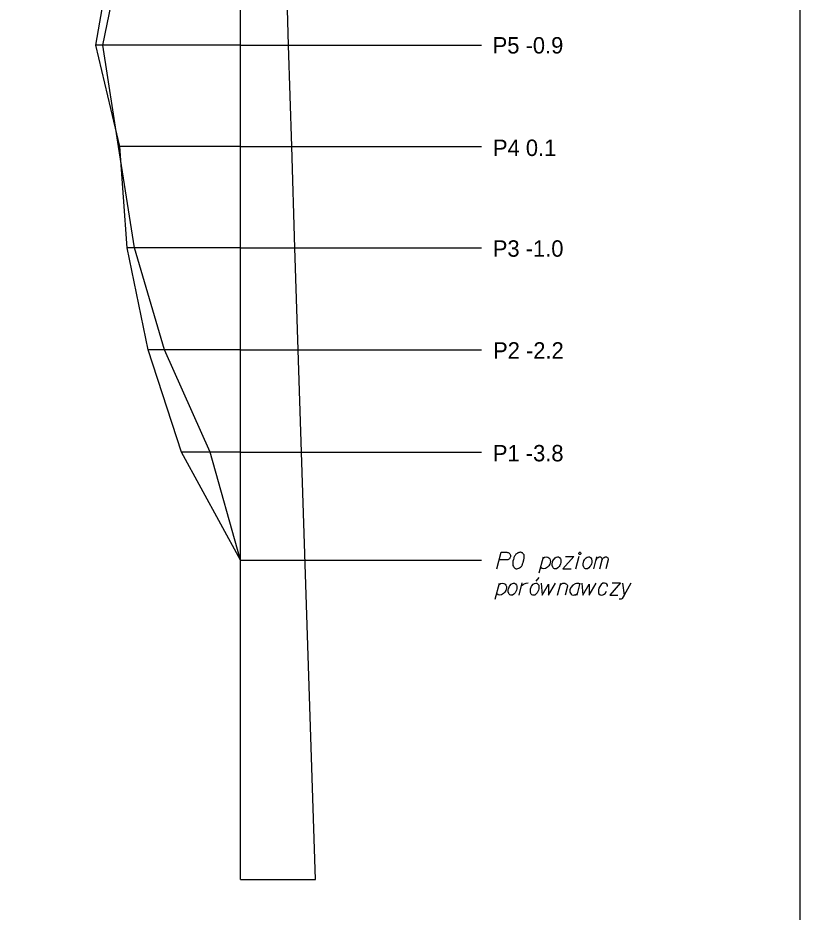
# Model space of a CAD drawing. Extents: x 138 to 264, y -75 to 121.
# Drawn here: x 206.91 to 217.41, y -57.33 to -45.34 of the extents above; entities that cross this region are included whole.
import ezdxf

# ---------------------------------------------------------------- set-up
doc = ezdxf.new("R2010")
doc.units = 0
for name, color, linetype in [('15 listopad 2008', 7, 'Continuous'), ('Ramka do drukowania', 7, 'Continuous'), ('Standart wykresów', 7, 'Continuous'), ('Wykresy 4 maj 2008', 7, 'Continuous')]:
    doc.layers.add(name, color=color, linetype=linetype)

msp = doc.modelspace()

# ---------------------------------------------------------------- linework, layer by layer
at = {"layer": '15 listopad 2008'}
msp.add_lwpolyline([(209.897, -52.61), (209.107, -51.164), (208.657, -49.788), (208.377, -48.421), (208.277, -47.063), (207.957, -45.704), (208.197, -44.313), (208.427, -42.911), (208.387, -41.918), (208.237, -40.937), (208.377, -40.478), (207.757, -39.961), (207.377, -39.493), (206.327, -38.925), (205.867, -38.4), (205.357, -38.212), (202.267, -37.514), (200.467, -37.151), (198.667, -36.895)], dxfattribs=at)
at = {"layer": 'Ramka do drukowania'}
msp.add_line((217.41, -63.621), (217.41, -33.921), dxfattribs=at)
at = {"layer": 'Standart wykresów'}
for p, q in [((209.897, -56.895), (209.897, -36.811)), ((210.544, -45.704), (210.5, -44.313)), ((209.897, -45.704), (213.134, -45.704)), ((210.587, -47.063), (210.544, -45.704)), ((209.897, -47.063), (213.134, -47.063)), ((210.629, -48.421), (210.587, -47.063)), ((209.897, -48.421), (213.134, -48.421)), ((210.671, -49.788), (210.629, -48.421)), ((209.897, -49.788), (213.134, -49.788)), ((210.716, -51.164), (210.671, -49.788)), ((209.897, -51.164), (209.107, -51.164)), ((209.897, -51.164), (213.134, -51.164)), ((210.904, -56.895), (210.716, -51.164)), ((209.897, -52.61), (213.134, -52.61)), ((209.897, -56.895), (210.904, -56.895))]:
    msp.add_line(p, q, dxfattribs=at)
for points in [[(213.341, -52.725), (213.399, -52.505), (213.474, -52.505), (213.484, -52.507), (213.489, -52.509), (213.5, -52.514), (213.507, -52.519), (213.512, -52.526), (213.517, -52.535), (213.521, -52.547), (213.522, -52.557), (213.521, -52.566), (213.519, -52.573), (213.515, -52.58), (213.512, -52.585), (213.507, -52.592), (213.5, -52.597), (213.495, -52.6), (213.486, -52.604), (213.477, -52.606), (213.373, -52.606)], [(213.656, -52.505), (213.652, -52.505), (213.642, -52.507), (213.635, -52.509), (213.63, -52.51), (213.621, -52.514), (213.611, -52.519), (213.602, -52.524), (213.593, -52.531), (213.588, -52.538), (213.583, -52.547), (213.578, -52.555), (213.573, -52.566), (213.569, -52.573), (213.566, -52.583), (213.561, -52.6), (213.555, -52.626), (213.552, -52.647), (213.552, -52.666), (213.554, -52.68), (213.561, -52.696), (213.566, -52.704), (213.574, -52.715), (213.585, -52.722), (213.59, -52.723), (213.6, -52.725), (213.609, -52.725), (213.623, -52.723), (213.635, -52.72), (213.644, -52.715), (213.656, -52.706), (213.661, -52.701), (213.668, -52.694), (213.673, -52.687), (213.677, -52.682), (213.68, -52.673), (213.682, -52.67), (213.685, -52.661), (213.689, -52.651), (213.692, -52.64), (213.694, -52.633), (213.696, -52.628), (213.697, -52.621), (213.701, -52.606), (213.703, -52.597), (213.704, -52.588), (213.706, -52.576), (213.708, -52.56), (213.708, -52.555), (213.706, -52.548), (213.704, -52.541), (213.699, -52.531), (213.694, -52.524), (213.689, -52.519), (213.682, -52.514), (213.675, -52.51), (213.67, -52.509), (213.664, -52.507), (213.656, -52.505)], [(214.449, -52.505), (214.458, -52.505), (214.463, -52.509), (214.468, -52.515), (214.468, -52.524), (214.463, -52.531), (214.458, -52.535), (214.449, -52.535), (214.444, -52.531), (214.439, -52.524), (214.439, -52.515), (214.444, -52.509), (214.449, -52.505)], [(213.907, -52.782), (213.966, -52.566)], [(213.961, -52.585), (213.978, -52.571), (214.004, -52.566), (214.025, -52.569), (214.039, -52.58), (214.049, -52.593), (214.056, -52.612), (214.058, -52.63), (214.054, -52.645), (214.049, -52.664), (214.035, -52.685), (214.018, -52.704), (213.992, -52.722), (213.969, -52.725), (213.948, -52.723), (213.926, -52.711)], [(214.155, -52.566), (214.167, -52.566), (214.181, -52.573), (214.194, -52.592), (214.196, -52.6), (214.198, -52.609), (214.198, -52.616), (214.198, -52.642), (214.193, -52.659), (214.184, -52.68), (214.174, -52.697), (214.156, -52.713), (214.141, -52.725), (214.115, -52.725), (214.104, -52.722), (214.094, -52.713), (214.089, -52.704), (214.082, -52.683), (214.082, -52.652), (214.085, -52.642), (214.092, -52.619), (214.099, -52.607), (214.103, -52.6), (214.12, -52.581), (214.137, -52.571), (214.155, -52.566)], [(214.259, -52.562), (214.371, -52.562), (214.227, -52.725), (214.338, -52.725)], [(214.401, -52.725), (214.446, -52.557)], [(214.57, -52.566), (214.582, -52.566), (214.596, -52.573), (214.61, -52.592), (214.612, -52.6), (214.614, -52.609), (214.614, -52.616), (214.614, -52.642), (214.608, -52.659), (214.6, -52.68), (214.589, -52.697), (214.572, -52.713), (214.556, -52.725), (214.531, -52.725), (214.52, -52.722), (214.51, -52.713), (214.505, -52.704), (214.498, -52.683), (214.498, -52.652), (214.501, -52.642), (214.508, -52.619), (214.515, -52.607), (214.518, -52.6), (214.536, -52.581), (214.553, -52.571), (214.57, -52.566)], [(214.643, -52.725), (214.683, -52.567)], [(214.673, -52.609), (214.681, -52.59), (214.69, -52.58), (214.7, -52.573), (214.711, -52.567), (214.718, -52.564), (214.728, -52.564), (214.731, -52.566), (214.738, -52.573), (214.745, -52.581), (214.75, -52.597), (214.752, -52.606), (214.761, -52.59), (214.771, -52.58), (214.782, -52.573), (214.792, -52.567), (214.801, -52.564), (214.809, -52.564), (214.816, -52.566), (214.822, -52.573), (214.827, -52.581), (214.832, -52.597), (214.834, -52.606), (214.804, -52.725)], [(214.723, -52.725), (214.752, -52.606)], [(213.905, -52.843), (213.861, -52.891)], [(213.318, -53.135), (213.376, -52.919)], [(213.371, -52.938), (213.389, -52.924), (213.415, -52.919), (213.435, -52.922), (213.449, -52.933), (213.46, -52.947), (213.467, -52.966), (213.468, -52.983), (213.465, -52.999), (213.46, -53.018), (213.446, -53.038), (213.428, -53.057), (213.402, -53.075), (213.38, -53.078), (213.359, -53.077), (213.337, -53.064)], [(213.565, -52.919), (213.577, -52.919), (213.591, -52.926), (213.605, -52.945), (213.607, -52.954), (213.609, -52.962), (213.609, -52.969), (213.609, -52.995), (213.603, -53.012), (213.595, -53.033), (213.584, -53.051), (213.567, -53.066), (213.551, -53.078), (213.525, -53.078), (213.515, -53.075), (213.505, -53.066), (213.499, -53.057), (213.492, -53.037), (213.492, -53.006), (213.496, -52.995), (213.503, -52.973), (213.51, -52.96), (213.513, -52.954), (213.531, -52.934), (213.548, -52.924), (213.565, -52.919)], [(213.638, -53.078), (213.681, -52.914)], [(213.671, -52.954), (213.68, -52.947), (213.699, -52.933), (213.719, -52.924), (213.735, -52.919), (213.759, -52.914)], [(213.861, -52.919), (213.874, -52.919), (213.887, -52.926), (213.901, -52.945), (213.903, -52.954), (213.905, -52.962), (213.905, -52.969), (213.905, -52.995), (213.9, -53.012), (213.891, -53.033), (213.88, -53.051), (213.863, -53.066), (213.848, -53.078), (213.822, -53.078), (213.811, -53.075), (213.801, -53.066), (213.796, -53.057), (213.789, -53.037), (213.789, -53.006), (213.792, -52.995), (213.799, -52.973), (213.806, -52.96), (213.809, -52.954), (213.827, -52.934), (213.844, -52.924), (213.861, -52.919)], [(213.934, -52.921), (213.948, -53.078), (214.031, -52.934), (214.033, -53.078), (214.125, -52.917)], [(214.154, -53.078), (214.197, -52.919)], [(214.187, -52.957), (214.192, -52.948), (214.199, -52.938), (214.204, -52.933), (214.211, -52.926), (214.218, -52.922), (214.227, -52.919), (214.236, -52.917), (214.243, -52.917), (214.251, -52.919), (214.258, -52.922), (214.265, -52.926), (214.272, -52.931), (214.279, -52.938), (214.282, -52.943), (214.286, -52.95), (214.289, -52.959), (214.258, -53.078)], [(214.449, -52.933), (214.437, -52.924), (214.407, -52.924), (214.39, -52.928), (214.359, -52.945), (214.333, -52.976), (214.32, -53.009), (214.319, -53.026), (214.32, -53.04), (214.326, -53.052), (214.336, -53.066), (214.348, -53.075), (214.367, -53.078), (214.381, -53.077), (214.395, -53.075), (214.414, -53.064)], [(214.452, -52.919), (214.411, -53.078)], [(214.482, -52.921), (214.495, -53.078), (214.579, -52.934), (214.58, -53.078), (214.672, -52.917)], [(214.825, -52.966), (214.823, -52.945), (214.814, -52.931), (214.804, -52.924), (214.783, -52.921), (214.764, -52.921), (214.74, -52.936), (214.721, -52.962), (214.707, -52.988), (214.702, -53.007), (214.702, -53.037), (214.703, -53.047), (214.71, -53.061), (214.726, -53.075), (214.743, -53.078), (214.762, -53.077), (214.773, -53.073), (214.795, -53.057), (214.812, -53.028)], [(214.885, -52.915), (214.998, -52.915), (214.854, -53.078), (214.965, -53.078)], [(215.138, -52.917), (215.05, -53.078), (215.022, -53.125), (215.015, -53.129), (215.006, -53.132), (214.989, -53.135), (214.982, -53.135)], [(215.027, -52.919), (215.05, -53.078)]]:
    msp.add_lwpolyline(points, dxfattribs=at)
at = {"layer": 'Wykresy 4 maj 2008'}
for p, q in [((209.897, -45.704), (207.957, -45.704)), ((209.897, -47.063), (208.263, -47.063)), ((209.897, -48.421), (208.377, -48.421)), ((209.897, -49.788), (208.657, -49.788))]:
    msp.add_line(p, q, dxfattribs=at)
msp.add_lwpolyline([(209.897, -52.61), (209.49, -51.164), (208.88, -49.788), (208.475, -48.421), (208.263, -47.063), (208.05, -45.704), (208.338, -44.313), (208.516, -42.911), (208.223, -41.918), (208.116, -40.937), (208.024, -40.478), (207.528, -39.961), (207.135, -39.493), (206.14, -38.925), (205.674, -38.4), (205.36, -38.212), (202.317, -37.514), (200.558, -37.151), (198.761, -36.895)], dxfattribs=at)

# ---------------------------------------------------------------- texts
for s, p in [('P5 -0.9', (213.283, -45.814)), ('P4 0.1', (213.287, -47.189)), ('P3 -1.0', (213.285, -48.54)), ('P2 -2.2', (213.289, -49.907)), ('P1 -3.8', (213.286, -51.285))]:
    msp.add_text(s, height=0.22, dxfattribs=at).set_placement(p)

doc.saveas('drawing.dxf')
